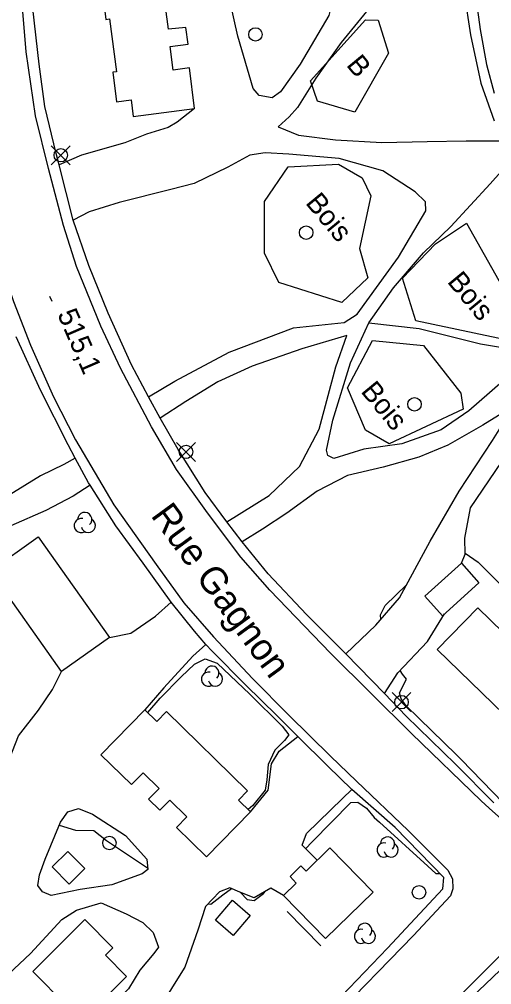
# Model space of a CAD drawing. Extents: x 347312 to 350503, y 6073086 to 6076432.
# Drawn here: x 348519.3 to 348589.5, y 6074723.1 to 6074866.6 of the extents above; entities that cross this region are included whole.
import ezdxf

# ---------------------------------------------------------------- set-up
doc = ezdxf.new("R2010")
doc.units = 0
for name, color, linetype in [('Level 19', 7, 'Continuous'), ('Level 2', 7, 'Continuous'), ('Level 21', 7, 'Continuous'), ('Level 22', 7, 'Continuous'), ('Level 3', 7, 'Continuous'), ('Level 31', 7, 'Continuous'), ('Level 36', 7, 'Continuous'), ('Level 37', 7, 'Continuous'), ('Level 44', 7, 'Continuous')]:
    doc.layers.add(name, color=color, linetype=linetype)

msp = doc.modelspace()

# ---------------------------------------------------------------- linework, layer by layer
at = {"layer": 'Level 19'}
for points in [[(348585.18, 6074874), (348580.52, 6074873), (348576.06, 6074872.21), (348574.86, 6074872.03), (348573.76, 6074871.27), (348571.97, 6074869.1), (348567.12, 6074863.2), (348563.36, 6074857.89), (348560.62, 6074853.52), (348559.39, 6074852.11), (348557.76, 6074850.63), (348560.8, 6074849.41), (348566.27, 6074848.71), (348573.2, 6074848.33), (348579.93, 6074848.46), (348585.72, 6074848.55), (348591.02, 6074848.58)], [(348557.96, 6074873.04), (348562.21, 6074872.24), (348565.68, 6074872.05), (348566.24, 6074871.01), (348565.28, 6074867.21), (348561.05, 6074859.94), (348558.09, 6074855.83), (348556.86, 6074854.96), (348554.93, 6074855.3), (348554.04, 6074856.36), (348551.76, 6074864.14), (348550.68, 6074868.97), (348551.32, 6074870.18), (348553.09, 6074870.72)], [(348545.34, 6074853.35), (348542.73, 6074851.36), (348541.39, 6074850.54), (348538.18, 6074849.53), (348534.95, 6074848.26), (348528.52, 6074846.43), (348525.19, 6074845.02)], [(348538.49, 6074810.49), (348542.39, 6074812.83), (348550.49, 6074817.17), (348560.04, 6074820.76), (348567.57, 6074821.55), (348569.53, 6074822.81), (348575.67, 6074831.29), (348579.7, 6074838.17), (348579.65, 6074839.48), (348578.11, 6074840.97), (348573.31, 6074844.11), (348566.81, 6074845.96), (348559.36, 6074846.59), (348555.82, 6074846.79), (348553.57, 6074846.42), (348550.3, 6074844.67), (348545.28, 6074842.22), (348541.8, 6074841.35), (348534.12, 6074839.39), (348529.65, 6074837.99), (348527.31, 6074836.78)], [(348606.51, 6074824.13), (348602.54, 6074821.36), (348595.92, 6074817.05), (348592.66, 6074814.11), (348586.12, 6074808.45), (348582.01, 6074805.63), (348576.17, 6074803.54), (348570.52, 6074802.74), (348566.05, 6074801.35), (348565.15, 6074801.8), (348564.94, 6074802.59), (348565.88, 6074807.05), (348568.54, 6074815.56), (348571.22, 6074821.53), (348574.93, 6074826.72), (348579.38, 6074831.92), (348583.42, 6074835.81), (348589.29, 6074842.19), (348590.93, 6074844.01), (348592.49, 6074845.07)], [(348585, 6074785.78), (348585.56, 6074787.11), (348585.53, 6074789.48), (348586.35, 6074793.99), (348590.95, 6074800.81), (348594.99, 6074806.97), (348600.04, 6074813.88), (348604.99, 6074817.77), (348609.44, 6074821.25)], [(348550.15, 6074791.91), (348556.41, 6074795.84), (348560.94, 6074800.14), (348563.87, 6074805.72), (348566.35, 6074814.98), (348567.96, 6074819.62), (348561.27, 6074817.65), (348553.9, 6074815.05), (348548.78, 6074812.73), (348544.05, 6074809.84), (348540.22, 6074807.32)], [(348567.83, 6074772.29), (348572.28, 6074776.59), (348575.8, 6074780.64), (348580.34, 6074789.06), (348584.66, 6074796.48), (348589.65, 6074804), (348592.83, 6074809.19), (348588.18, 6074806.3), (348582.99, 6074803.34), (348578.69, 6074801.56), (348573.35, 6074800.04), (348568.07, 6074798.8), (348563.56, 6074796.47), (348559.05, 6074793.24), (348555.43, 6074790.82), (348552.39, 6074788.98)], [(348527.61, 6074801.41), (348525.92, 6074800.45), (348522.45, 6074798.76), (348517.8, 6074795.9)], [(348529.83, 6074797.36), (348527.3, 6074795.76), (348523.21, 6074793.64), (348518.01, 6074791.33), (348513.7, 6074790.37), (348510.03, 6074789.8), (348507.58, 6074788.96), (348504.09, 6074786.66), (348502.02, 6074784.63), (348499.75, 6074781.24), (348495.67, 6074774.7), (348492.12, 6074770.32), (348489.05, 6074767.7), (348483.32, 6074762.33), (348481.8, 6074761.19)], [(348532.71, 6074774.74), (348535.84, 6074775.4), (348539.51, 6074777.93), (348541.85, 6074779.99)], [(348573.57, 6074766.43), (348575.54, 6074769.49), (348579.97, 6074774.15), (348582.5, 6074778.26)], [(348547.03, 6074773.72), (348545.09, 6074771.96), (348540.77, 6074767.24), (348537.96, 6074764)], [(348495.85, 6074741.6), (348500.13, 6074743.22), (348511.2, 6074747.03), (348513.11, 6074748.17), (348516.48, 6074753.3), (348519.19, 6074760.12), (348522.16, 6074763.94), (348524.2, 6074766.99), (348525.58, 6074769.68)], [(348553.63, 6074748.84), (348556.3, 6074752.04), (348556.78, 6074755.96), (348557.9, 6074757.86), (348560.71, 6074760)], [(348563.56, 6074741.62), (348561.31, 6074743.87), (348561.96, 6074745.61), (348567.31, 6074750.8), (348568.74, 6074752.16)], [(348523.11, 6074741.8), (348525.42, 6074747.31), (348526.5, 6074748.81), (348528.1, 6074749.32), (348530.15, 6074748.48), (348535.06, 6074745.29), (348538.26, 6074741.81), (348538.37, 6074740.25), (348537.57, 6074739.59), (348533.04, 6074738), (348528.31, 6074737.28), (348524.01, 6074736.4), (348522.75, 6074736.93), (348522.02, 6074737.89), (348522.29, 6074739.46), (348523.11, 6074741.8)], [(348558.56, 6074736.38), (348556.66, 6074737.49), (348554.19, 6074736.04), (348552.06, 6074736.89), (348550.6, 6074737.55), (348549.03, 6074736.92), (348546.98, 6074734.74), (348545.82, 6074731.24), (348543.91, 6074725.75), (348542.82, 6074724.01), (348540.15, 6074719.71), (348535.53, 6074715.21), (348532.73, 6074712.79), (348528.46, 6074707.6)], [(348513.67, 6074721.87), (348516.89, 6074723.94), (348520.96, 6074727.78), (348525.6, 6074732.84), (348527.77, 6074734.19), (348531.43, 6074735.29), (348535.17, 6074733.68), (348537.63, 6074732.36), (348539.17, 6074730.87), (348540, 6074728.71), (348539.3, 6074727.75), (348537.2, 6074725.28), (348535.52, 6074722.5), (348529.09, 6074716.11), (348524.69, 6074711.26)]]:
    msp.add_lwpolyline(points, dxfattribs=at)
at = {"layer": 'Level 2'}
for points in [[(348585.56, 6074787.25), (348587.5, 6074785.96), (348599.45, 6074774), (348604.99, 6074769), (348609.16, 6074764.4), (348609.2, 6074764.35)], [(348573, 6074778.12), (348573.68, 6074779.5), (348576.83, 6074782.56)], [(348573.01, 6074777.43), (348573, 6074778.12)], [(348538.4, 6074763.57), (348540.23, 6074765.72), (348543.34, 6074768.87), (348545.31, 6074770.76), (348546.9, 6074771.56), (348548.7, 6074770.93), (348553.57, 6074766.33), (348558.34, 6074761.57), (348559.34, 6074760.27), (348558.69, 6074759.42), (348557.25, 6074757.98), (348556.29, 6074755.87), (348556.09, 6074753.57), (348555.83, 6074752.06), (348553.99, 6074749.75), (348553.29, 6074749.18)], [(348591.01, 6074749.1), (348591.28, 6074749.43), (348591.21, 6074750.16), (348584.99, 6074756.62), (348584.23, 6074757.33), (348580.6, 6074760.85), (348576.81, 6074764.56), (348576.03, 6074765.63), (348575.81, 6074766.51), (348576.86, 6074768.54), (348576.25, 6074769.28), (348575.88, 6074769.85)], [(348561.85, 6074743.33), (348562.83, 6074744.36), (348568.59, 6074750.21), (348569.6, 6074750.27), (348570.89, 6074749.37), (348572.04, 6074747.97), (348572.85, 6074747.3), (348580.02, 6074740.75), (348581.22, 6074739.64), (348581.72, 6074739.64), (348581.77, 6074739.68)], [(348525.22, 6074746.83), (348527.66, 6074746.12), (348530.37, 6074746.03), (348532.26, 6074744.58), (348538.35, 6074740.49)], [(348547.39, 6074735.17), (348547.78, 6074735.12), (348549.54, 6074736.49), (348550.82, 6074737.45)], [(348552.17, 6074736.84), (348553.14, 6074735.82), (348554.2, 6074735.66), (348555.57, 6074736.7), (348555.89, 6074737.04)]]:
    msp.add_lwpolyline(points, dxfattribs=at)
at = {"layer": 'Level 21'}
for points in [[(348589.8, 6074904.87), (348588.23, 6074895.39), (348587, 6074888.21), (348586.71, 6074885.04), (348586.43, 6074880.61), (348586.65, 6074875.76), (348586.99, 6074871.02), (348587.8, 6074865.09), (348588.73, 6074859.93), (348589.89, 6074855.65)], [(348591.91, 6074746.91), (348589.12, 6074749.39), (348587.94, 6074750.44), (348577.59, 6074760.49), (348565.53, 6074772.42), (348556.51, 6074781.78), (348552.21, 6074786.67), (348547.24, 6074793.26), (348542.67, 6074799.72), (348538.95, 6074806.07), (348534.33, 6074814.75), (348531.42, 6074821.03), (348527.81, 6074829.87), (348525.86, 6074835.97), (348523.61, 6074844.44), (348521.7, 6074852.3), (348520.32, 6074861.8), (348519.54, 6074870.83)], [(348508.91, 6074868.02), (348509.93, 6074859.87), (348510.51, 6074854.49), (348512.69, 6074843.87), (348514.73, 6074835.74), (348518.4, 6074824.7), (348520.96, 6074818.2), (348524.39, 6074810.49), (348527.66, 6074804.14), (348533.33, 6074794.46), (348539.61, 6074785.59), (348543.76, 6074779.9), (348548.13, 6074774.84), (348553.96, 6074768.67), (348559.35, 6074763.19), (348565.56, 6074757.11), (348569.41, 6074753.39)], [(348569.41, 6074753.39), (348577.08, 6074746.03), (348582.98, 6074740.17), (348583.69, 6074738.86), (348583.72, 6074737.37), (348583.39, 6074736.32), (348577.87, 6074730.47), (348565.56, 6074717.75)], [(348688.87, 6074636.16), (348678.14, 6074646.5), (348668.15, 6074656.39), (348660.76, 6074663.78), (348650.03, 6074674.29), (348640.28, 6074683.72), (348627.62, 6074696.19), (348616.16, 6074707.4), (348606.77, 6074716.48), (348595.12, 6074727.93), (348593.78, 6074728.63), (348593.12, 6074728.61), (348592.12, 6074728.46), (348591.04, 6074727.77), (348583.93, 6074720.65), (348571.99, 6074708.48), (348566.32, 6074702.72), (348556.37, 6074692.61), (348551.14, 6074687.28)]]:
    msp.add_lwpolyline(points, dxfattribs=at)
at = {"layer": 'Level 22'}
for points in [[(348585.4, 6074870.5), (348586.35, 6074864.32), (348587.91, 6074857.14), (348589.86, 6074851.56)], [(348589.84, 6074750.15), (348584.14, 6074755.89), (348576.81, 6074763.06), (348573.57, 6074766.43), (348567.83, 6074772.29), (348561.97, 6074778.14), (348556.3, 6074784.21), (348552.39, 6074788.98), (348550.15, 6074791.91), (348546.92, 6074796.27), (348542.92, 6074802.69), (348540.22, 6074807.32), (348538.49, 6074810.49), (348535.95, 6074815.26), (348532.48, 6074822.94), (348529.64, 6074830.02), (348527.31, 6074836.78), (348525.19, 6074845.02), (348524.77, 6074846.66), (348523.07, 6074853.65), (348522.22, 6074859.98), (348521.29, 6074868.21)], [(348571.22, 6074821.53), (348578.71, 6074820.66), (348587.82, 6074818.38), (348595.92, 6074817.05)], [(348568.74, 6074752.16), (348565.14, 6074755.59), (348560.71, 6074760), (348557.56, 6074763.15), (348552.97, 6074767.65), (348547.95, 6074772.69), (348547.03, 6074773.72), (348545.31, 6074775.67), (348541.85, 6074779.99), (348537.68, 6074785.8), (348533.64, 6074791.36), (348529.83, 6074797.36), (348529.59, 6074797.74), (348527.61, 6074801.41), (348526.54, 6074803.37), (348522.45, 6074811.51), (348518.84, 6074819.45)], [(348562.6, 6074716.66), (348574.02, 6074728.54), (348582.26, 6074737.38), (348582.37, 6074739.07), (348575.16, 6074746.5), (348568.74, 6074752.16)], [(348591.1, 6074646.15), (348586.84, 6074650.39), (348580.19, 6074656.96), (348573.86, 6074662.97), (348568.45, 6074668.22), (348558.4, 6074677.8), (348551.97, 6074684.19), (348551.46, 6074684.9), (348551.38, 6074685.45), (348553.3, 6074687.67), (348557.03, 6074691.41), (348564.3, 6074698.6), (348568.7, 6074703.06), (348571.23, 6074705.64), (348578.7, 6074713.14), (348587.57, 6074722.2), (348591.79, 6074726.27)]]:
    msp.add_lwpolyline(points, dxfattribs=at)
at = {"layer": 'Level 3'}
msp.add_line((348523.78, 6074825.47), (348524.1, 6074824.74), dxfattribs=at)
at = {"layer": 'Level 31'}
for points in [[(348541.46, 6074865.16), (348541.04, 6074868.47), (348543.39, 6074868.77), (348542.59, 6074874.99), (348533.44, 6074873.81), (348533.75, 6074871.37), (348531.59, 6074871.09), (348532.17, 6074866.62), (348532.71, 6074866.69), (348533.72, 6074858.82), (348533.18, 6074858.75), (348533.74, 6074854.38), (348535.9, 6074854.66), (348536.22, 6074852.17), (348545.34, 6074853.35), (348544.57, 6074859.4), (348542.15, 6074859.08), (348541.69, 6074862.6), (348544.37, 6074862.95), (348544.05, 6074865.42), (348541.46, 6074865.16)], [(348522.09, 6074789.7), (348532.71, 6074774.74), (348525.58, 6074769.68), (348514.96, 6074784.65), (348522.09, 6074789.7)], [(348579.57, 6074780.89), (348585, 6074785.78), (348587.62, 6074782.88), (348582.18, 6074777.98), (348579.57, 6074780.89)], [(348594.66, 6074760.07), (348581.42, 6074772.98), (348587.45, 6074779.17), (348600.7, 6074766.25), (348594.66, 6074760.07)], [(348537.68, 6074754.63), (348535.95, 6074752.87), (348531.42, 6074757.3), (348537.96, 6074764), (348539.74, 6074762.26), (348541.17, 6074763.72), (348553.23, 6074751.94), (348551.88, 6074750.56), (348553.63, 6074748.84), (348547.1, 6074742.15), (348542.64, 6074746.51), (348544.19, 6074748.1), (348541.66, 6074750.58), (348540.18, 6074749.07), (348538.51, 6074750.7), (348540.07, 6074752.3), (348537.68, 6074754.63)], [(348559.54, 6074739.2), (348561.16, 6074740.78), (348561.91, 6074740.01), (348565.45, 6074743.46), (348571.87, 6074736.88), (348564.79, 6074729.98), (348558.56, 6074736.38), (348560.46, 6074738.23), (348559.54, 6074739.2)], [(348529.03, 6074740.42), (348526.69, 6074738.1), (348524.18, 6074740.64), (348526.51, 6074742.95), (348529.03, 6074740.42)], [(348553.62, 6074733.43), (348551.07, 6074730.45), (348548.44, 6074732.7), (348550.99, 6074735.68), (348553.62, 6074733.43)], [(348526.3, 6074720.06), (348521.29, 6074725.07), (348529.03, 6074732.8), (348533.19, 6074728.62), (348532.09, 6074727.52), (348535.23, 6074724.37), (348529.39, 6074718.53), (348527.09, 6074720.84), (348526.3, 6074720.06)]]:
    msp.add_lwpolyline(points, dxfattribs=at)
at = {"layer": 'Level 36'}
for p, q in [((348524.04, 6074845.01), (348526.86, 6074847.83)), ((348524.04, 6074847.83), (348526.86, 6074845.01)), ((348542.66, 6074800.92), (348545.48, 6074803.74)), ((348542.66, 6074803.74), (348545.48, 6074800.92)), ((348574.69, 6074763.72), (348577.51, 6074766.54)), ((348574.69, 6074766.54), (348577.51, 6074763.72))]:
    msp.add_line(p, q, dxfattribs=at)
for centre in [(348554.39, 6074864.38), (348525.45, 6074846.42), (348561.93, 6074834.92), (348578.03, 6074809.4), (348544.07, 6074802.33), (348576.1, 6074765.13), (348532.68, 6074744.2), (348578.71, 6074736.86)]:
    msp.add_circle(centre, 1, dxfattribs=at)
at = {"layer": 'Level 37'}
msp.add_lwpolyline([(348559.09, 6074734.02), (348564.1, 6074728.91)], dxfattribs=at)
at = {"layer": 'Level 44'}
for points in [[(348574.15, 6074861.6), (348569.17, 6074852.81), (348563.59, 6074854.46), (348562.55, 6074857.5), (348570.76, 6074866.57), (348572.63, 6074866.48), (348574.15, 6074861.6)], [(348571.56, 6074840.41), (348569.86, 6074832.55), (348571.1, 6074828.18), (348567.24, 6074824.53), (348557.85, 6074827.5), (348555.71, 6074831.87), (348555.75, 6074839.55), (348559.26, 6074844.71), (348566.75, 6074845.1), (348570.25, 6074843.06), (348571.56, 6074840.41)], [(348585.77, 6074836.34), (348594.72, 6074820.41), (348593, 6074818.68), (348578.22, 6074821.82), (348576.25, 6074828.13), (348581.14, 6074833.25), (348585.77, 6074836.34)], [(348571.8, 6074818.88), (348579.35, 6074818.12), (348584.93, 6074811.07), (348585.29, 6074808.67), (348574.25, 6074803.53), (348570.75, 6074805.57), (348568.05, 6074811.86), (348571.8, 6074818.88)]]:
    msp.add_lwpolyline(points, dxfattribs=at)
for centre, start, end in [((348528.49, 6074791.38), 76.8848, 299.5691), ((348529.01, 6074792.28), 314.0633, 179.7519), ((348529.54, 6074791.38), 192.2171, 59.6742), ((348547.4, 6074768.54), 76.8848, 299.5691), ((348547.92, 6074769.44), 314.0633, 179.7519), ((348548.45, 6074768.54), 192.2171, 59.6742), ((348574.03, 6074744.05), 314.0633, 179.7519), ((348573.51, 6074743.15), 76.8848, 299.5691), ((348574.56, 6074743.15), 192.2171, 59.6742), ((348570.65, 6074731.22), 314.0633, 179.7519), ((348570.13, 6074730.32), 76.8848, 299.5691), ((348571.18, 6074730.32), 192.2171, 59.6742)]:
    msp.add_arc(centre, 1.05, start, end, dxfattribs=at)

# ---------------------------------------------------------------- texts
at = {"layer": 'Level 21'}
msp.add_text('Rue Gagnon', height=4, rotation=306.2257, dxfattribs=at).set_placement((348538.73, 6074792.85))
at = {"layer": 'Level 3'}
msp.add_text('515,1', height=3, rotation=293.4641, dxfattribs=at).set_placement((348524.89, 6074822.82))
at = {"layer": 'Level 44'}
for s, p in [('B', (348567.79, 6074859.8)), ('Bois', (348561.72, 6074839.3)), ('Bois', (348582.79, 6074827.59)), ('Bois', (348569.94, 6074811.28))]:
    msp.add_text(s, height=3, rotation=309.568, dxfattribs=at).set_placement(p)

doc.saveas('drawing.dxf')
